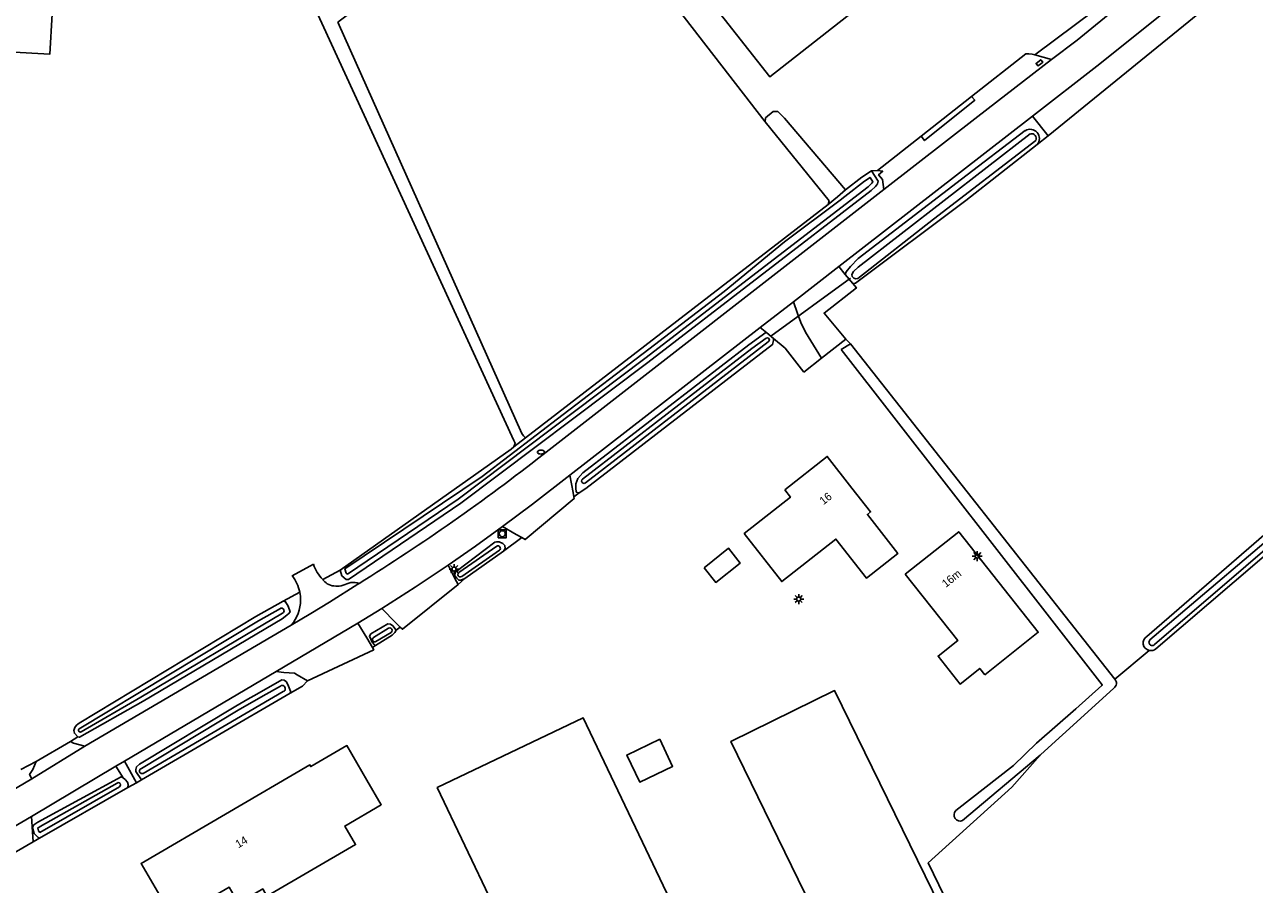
# Model space of a CAD drawing. Extents: x 141000 to 143000, y 400580 to 403500.
# Drawn here: x 141831.6 to 141985.3, y 403128.9 to 403236.3 of the extents above; entities that cross this region are included whole.
import ezdxf

# ---------------------------------------------------------------- set-up
doc = ezdxf.new("R2010")
doc.units = 0
for name, color, linetype in [('gg-afsc-erfafscheiding', 7, 'Continuous'), ('gg-anno-huisnummerreeks BGT', 7, 'Continuous'), ('gg-bbg-bijgebouw', 7, 'Continuous'), ('gg-bbg-gedigitaliseerde bebouwing', 7, 'Continuous'), ('gg-bbg-gedigitaliseerde bijgebouw', 7, 'Continuous'), ('gg-bbg-hoofdgebouw', 7, 'Continuous'), ('gg-knt-bronhoudergrens', 7, 'Continuous'), ('gg-knt-onverhard', 7, 'Continuous'), ('gg-knt-verharding', 7, 'Continuous'), ('gg-knt-verharding nz', 7, 'Continuous'), ('gg-kntw-bovenkant insteek waterloop', 7, 'Continuous'), ('gg-kntw-waterlijn', 7, 'Continuous'), ('gg-kwrk-duiker nz buis', 7, 'Continuous'), ('gt-grn-groengrens', 7, 'Continuous'), ('gt-grn-vlakafsluiter', 7, 'Continuous'), ('gt-symb-brandkraan', 7, 'Continuous'), ('gt-symb-kolk', 7, 'Continuous'), ('gt-symb-lichtmast', 7, 'Continuous'), ('gt-symb-rioolschacht', 7, 'Continuous'), ('gx-grn-maaiveld', 7, 'Continuous')]:
    doc.layers.add(name, color=color, linetype=linetype)

# ---------------------------------------------------------------- blocks, each defined once
blk = doc.blocks.new('gt0-KOLK')
at = {"layer": 'gt-symb-kolk'}
blk.add_lwpolyline([(0, 0), (0.37, 0), (0.37, 0.4), (-0.38, 0.4), (-0.38, 0), (0, 0)], dxfattribs=at)
blk = doc.blocks.new('gt0-LMAST')
at = {"layer": 'gt-symb-lichtmast'}
for p, q in [((-0.18, 0.17), (-0.45, 0.44)), ((-0.01, 0.25), (-0.01, 0.62)), ((0.17, 0.17), (0.44, 0.44)), ((-0.26, 0), (-0.63, 0)), ((-0.18, -0.18), (-0.45, -0.45)), ((-0.01, -0.25), (-0.01, -0.63)), ((0.44, -0.45), (0.17, -0.18)), ((0.24, 0), (0.62, 0))]:
    blk.add_line(p, q, dxfattribs=at)
blk.add_circle((-0.01, 0), 0.25, dxfattribs=at)
blk = doc.blocks.new('gt0-RS')
at = {"layer": 'gt-symb-rioolschacht'}
blk.add_lwpolyline([(-0.5, -0.5), (0.5, -0.5), (0.5, 0.5), (-0.5, 0.5)], close=True, dxfattribs=at)
blk.add_circle((0, 0), 0.375, dxfattribs=at)
blk = doc.blocks.new('gt0-BR')
at = {"layer": 'gt-symb-brandkraan'}
for centre, radius, start, end in [((-0.24, 0), 0.206, 107.5669, 252.4331), ((0.6, -2.66), 3, 106.892, 107.5669), ((0, -0.69), 0.938, 73.108, 106.892), ((-0.6, -2.66), 3, 72.4331, 73.108), ((0.24, 0), 0.206, 287.567, 72.4331), ((0.6, 2.66), 3, 252.4331, 253.108), ((0, 0.69), 0.938, 253.108, 286.8921), ((-0.6, 2.66), 3, 286.8921, 287.567)]:
    blk.add_arc(centre, radius, start, end, dxfattribs=at)

msp = doc.modelspace()

# ---------------------------------------------------------------- linework, layer by layer
at = {"layer": 'gg-afsc-erfafscheiding'}
for p, q in [((141900.92, 403177.77), (141900.27, 403177.27)), ((141891.48, 403170.47), (141893.77, 403172.17)), ((141871.09, 403168.12), (141868.9, 403166.93)), ((141885.81, 403166.33), (141886.65, 403167.08)), ((141866.02, 403165.36), (141863.93, 403164.22)), ((141878.05, 403160.62), (141878.59, 403160.98)), ((141875.11, 403158.45), (141875.49, 403158.68)), ((141838.3, 403147.27), (141837.37, 403146.71)), ((141833.1, 403144.23), (141831.19, 403143.2)), ((141845.64, 403141.56), (141846.26, 403141.91))]:
    msp.add_line(p, q, dxfattribs=at)
for points in [[(141866.97, 403154.3), (141866.35, 403153.64), (141864.84, 403152.76)], [(141832.7, 403134.18), (141833.19, 403134.45), (141833.5, 403134.63)]]:
    msp.add_lwpolyline(points, dxfattribs=at)
at = {"layer": 'gg-bbg-bijgebouw'}
for points in [[(141941.69, 403243.44), (141941.31, 403243.14), (141941.51, 403242.89), (141924.77, 403229.72), (141899.31, 403262.09), (141893.11, 403269.97), (141908.55, 403282.12), (141916.57, 403271.93), (141919.27, 403274.05), (141925.15, 403266.58)], [(141948.89, 403120.32), (141935.9, 403113.96), (141919.89, 403146.72), (141932.85, 403153.07), (141948.89, 403120.32)], [(141905.07, 403098.82), (141921.87, 403106.83), (141901.44, 403149.65), (141883.2, 403140.95), (141893.56, 403119.24), (141895, 403119.93), (141905.07, 403098.82)]]:
    msp.add_lwpolyline(points, dxfattribs=at)
at = {"layer": 'gg-bbg-gedigitaliseerde bebouwing'}
msp.add_lwpolyline([(141941.67, 403167.6), (141948.24, 403159.31), (141945.78, 403157.37), (141948.54, 403153.89), (141950.99, 403155.83), (141951.61, 403155.05)], dxfattribs=at)
at = {"layer": 'gg-bbg-gedigitaliseerde bijgebouw'}
for points in [[(141916.55, 403168.42), (141919.61, 403170.84), (141921.06, 403169), (141918, 403166.58), (141916.55, 403168.42)], [(141911, 403146.98), (141906.89, 403145.02), (141908.51, 403141.63), (141912.61, 403143.59), (141911, 403146.98)]]:
    msp.add_lwpolyline(points, dxfattribs=at)
at = {"layer": 'gg-bbg-hoofdgebouw'}
for points in [[(141834.07, 403278.36), (141836.96, 403278.24), (141836.92, 403277.43), (141835.07, 403237.57), (141834.8, 403232.58), (141823.57, 403233.19), (141823.73, 403237.19)], [(141926.62, 403178.14), (141927.33, 403177.21), (141921.56, 403172.68), (141926.24, 403166.69), (141933.01, 403171.99), (141936.82, 403167.11), (141940.76, 403170.2), (141936.95, 403175.07), (141937.35, 403175.39), (141935.02, 403178.37), (141931.94, 403182.31), (141926.62, 403178.14)], [(141951.61, 403155.05), (141958.31, 403160.36), (141948.37, 403172.91), (141941.67, 403167.6)], [(141861.92, 403127.39), (141872.99, 403133.84), (141871.64, 403136.15), (141876.21, 403138.81), (141874.42, 403141.87), (141871.92, 403146.19), (141867.4, 403143.58), (141867.29, 403143.78), (141846.19, 403131.47), (141850.28, 403124.47), (141857.21, 403128.51), (141858.37, 403126.52), (141861.4, 403128.29), (141861.92, 403127.39)]]:
    msp.add_lwpolyline(points, dxfattribs=at)
at = {"layer": 'gg-knt-bronhoudergrens'}
msp.add_line((141958.17, 403221.26), (141959.55, 403222.38), dxfattribs=at)
for points in [[(141924.18, 403224.13), (141898.5, 403257.31), (141870.76, 403236.56)], [(141958.55, 403144.99), (141955.02, 403141.02), (141944.55, 403131.54), (141954.01, 403112.06), (141957.01, 403108.48), (141960.13, 403104.76), (141962.3, 403102.46), (141965.5, 403098.58), (141966.12, 403097.9), (141967.07, 403095.33), (141975.4, 403078.56), (141957.18, 403069.55)]]:
    msp.add_lwpolyline(points, dxfattribs=at)
at = {"layer": 'gg-knt-onverhard'}
for p, q in [((141959.55, 403222.38), (141985.09, 403243.14)), ((141967.88, 403154.5), (141972.18, 403158.08))]:
    msp.add_line(p, q, dxfattribs=at)
at = {"layer": 'gg-knt-verharding'}
for p, q in [((141959.94, 403231.88), (141957.87, 403232.46)), ((141933.38, 403206.04), (141957.57, 403224.81)), ((141957.57, 403224.81), (141959.55, 403222.38)), ((141938.99, 403215.66), (141896.44, 403182.55)), ((141927.7, 403201.63), (141933.38, 403206.04)), ((141933.38, 403206.04), (141934.19, 403205.06)), ((141934.19, 403205.06), (141935.15, 403203.9)), ((141927.7, 403201.63), (141923.57, 403198.42)), ((141899.77, 403179.96), (141923.57, 403198.42)), ((141923.57, 403198.42), (141924.39, 403197.74)), ((141924.39, 403197.74), (141925.21, 403197.05)), ((141934.24, 403196.97), (141931.22, 403194.58)), ((141865.06, 403167.42), (141867.72, 403168.85)), ((141871.18, 403166.17), (141872.4, 403166.57)), ((141873.29, 403161.48), (141876.28, 403163.33)), ((141864.97, 403161.25), (141839.16, 403146.11)), ((141844.12, 403144.24), (141863.08, 403155.44)), ((141837.37, 403146.71), (141833.1, 403144.23)), ((141844.12, 403144.24), (141845.64, 403141.56)), ((141832.49, 403137.36), (141843.06, 403143.61)), ((141843.06, 403143.61), (141843.97, 403142.19)), ((141832.54, 403142.06), (141787.23, 403115.41)), ((141844.55, 403140.98), (141845.64, 403141.56))]:
    msp.add_line(p, q, dxfattribs=at)
for points in [[(141968.4, 403238.58), (141963.18, 403234.3), (141959.94, 403231.88)], [(141959.94, 403231.88), (141950.76, 403224.79), (141938.99, 403215.66)], [(141957.87, 403232.46), (141957.56, 403232.55), (141957.12, 403232.6), (141956.74, 403232.61)], [(141949.97, 403227.29), (141950.37, 403226.8), (141944.09, 403221.76), (141943.67, 403222.33)], [(141938.99, 403215.66), (141938.84, 403216.89), (141938.34, 403217.51), (141938.87, 403217.93), (141938.23, 403218.05)], [(141935.15, 403203.9), (141935.58, 403203.37), (141931.55, 403200.22), (141934.24, 403196.97)], [(141927.7, 403201.63), (141928.23, 403200.18), (141928.64, 403199.05)], [(141931.22, 403194.58), (141929.21, 403197.82), (141928.64, 403199.05)], [(141925.21, 403197.05), (141926.69, 403195.82), (141929.03, 403192.86)], [(141899.77, 403179.96), (141900.17, 403177.8), (141900.27, 403177.27)], [(141900.27, 403177.27), (141900.31, 403177.04), (141894.2, 403171.92), (141893.77, 403172.17)], [(141884.55, 403168.73), (141887.97, 403171.11), (141891.36, 403173.55)], [(141891.36, 403173.55), (141893.06, 403172.58), (141893.77, 403172.17)], [(141884.55, 403168.73), (141885.42, 403167.08), (141885.81, 403166.33)], [(141878.59, 403160.98), (141878.86, 403160.72), (141885.81, 403166.33)], [(141876.28, 403163.33), (141878.03, 403161.55), (141878.59, 403160.98)], [(141873.29, 403161.48), (141874.39, 403159.64), (141875.11, 403158.45)], [(141875.11, 403158.45), (141875.27, 403158.17), (141866.97, 403154.3)], [(141863.08, 403155.44), (141864.04, 403155.31), (141865.38, 403155.23), (141865.71, 403155.04), (141866.97, 403154.3)], [(141839.16, 403146.11), (141837.74, 403146.52), (141837.37, 403146.71)], [(141832.54, 403142.06), (141832.26, 403142.57), (141832.66, 403143.19), (141833.1, 403144.23)], [(141832.49, 403137.36), (141832.62, 403135.43), (141832.7, 403134.18)], [(141832.7, 403134.18), (141826.43, 403130.55), (141826.14, 403130.74)]]:
    msp.add_lwpolyline(points, dxfattribs=at)
for centre, radius, start, end in [((141735.06, 403388.54), 261.67, 301.923, 308.0774), ((141872.96, 403170.74), 5.57, 199.8394, 223.2194), ((141861.22, 403164.37), 4.91, 11.6057, 38.4918), ((141872.99, 403170.75), 5.6, 223.1468, 230.9856), ((141870.64, 403168.63), 2.52, 242.0676, 282.3455), ((141872.72, 403164.95), 1.64, 64.4544, 101.2682), ((141861.33, 403164.37), 4.79, 319.4025, 359.974), ((141861.21, 403164.37), 4.91, 359.9744, 11.5846)]:
    msp.add_arc(centre, radius, start, end, dxfattribs=at)
at = {"layer": 'gg-knt-verharding nz'}
for p, q in [((141863.08, 403155.44), (141873.29, 403161.48)), ((141839.16, 403146.11), (141832.54, 403142.06)), ((141843.06, 403143.61), (141844.12, 403144.24)), ((141823.9, 403132.28), (141832.49, 403137.36))]:
    msp.add_line(p, q, dxfattribs=at)
for points in [[(141957.57, 403224.81), (141965.64, 403231.07), (141973.71, 403237.51), (141983.27, 403245.36)], [(141891.36, 403173.55), (141895.12, 403176.35), (141899.77, 403179.96)], [(141876.28, 403163.33), (141880.44, 403165.99), (141884.55, 403168.73)], [(141873.43, 403166.44), (141873.27, 403166.34), (141869.72, 403164.13), (141867.42, 403162.69), (141864.97, 403161.25)]]:
    msp.add_lwpolyline(points, dxfattribs=at)
at = {"layer": 'gg-kntw-bovenkant insteek waterloop'}
for p, q in [((141932.03, 403213.79), (141894.24, 403184.64)), ((141935.15, 403203.9), (141935.48, 403203.95)), ((141933.67, 403195.66), (141934.83, 403196.37)), ((141967.88, 403154.5), (141934.83, 403196.37)), ((141886.65, 403167.08), (141891.48, 403170.47)), ((141967.74, 403153.38), (141964.04, 403150.01)), ((141846.26, 403141.91), (141864.84, 403152.76)), ((141958.63, 403145.07), (141964.04, 403150.01)), ((141958.55, 403144.99), (141948.83, 403136.84)), ((141844.55, 403140.98), (141833.5, 403134.63))]:
    msp.add_line(p, q, dxfattribs=at)
for points in [[(141892.76, 403183.52), (141892.92, 403183.97), (141892.78, 403184.3), (141859.92, 403255.74)], [(141870.76, 403236.56), (141893.76, 403185.18), (141894, 403184.88), (141894.24, 403184.64)], [(141924.18, 403224.13), (141924.24, 403224.6), (141925.18, 403225.42), (141925.76, 403225.39), (141926.61, 403224.55), (141934.22, 403215.6)], [(141924.18, 403224.13), (141932.16, 403214.26), (141932.03, 403213.79)], [(141956.67, 403223.01), (141948.7, 403216.94), (141935.81, 403207.03), (141934.86, 403206.06), (141934.3, 403205.38), (141934.19, 403205.06)], [(141958.17, 403221.26), (141949.25, 403214.27), (141935.48, 403203.95)], [(141871.09, 403168.12), (141871.3, 403167.41), (141871.82, 403166.96), (141872.11, 403166.96), (141886.17, 403176.47), (141909.51, 403194.05), (141937.41, 403215.53), (141937.97, 403216.04), (141938.21, 403216.38), (141938.3, 403216.7), (141937.45, 403218)], [(141937.45, 403218), (141936.24, 403217.18), (141934.22, 403215.6)], [(142018.46, 403199.94), (142002.95, 403186.55), (141991.15, 403176.51), (141971.88, 403159.84)], [(141900.92, 403177.77), (141900.58, 403177.86), (141900.51, 403178.39), (141900.52, 403178.91), (141900.78, 403179.57), (141901.4, 403180.27), (141922.14, 403196.26), (141924.28, 403197.8), (141924.39, 403197.74)], [(141900.92, 403177.77), (141901.76, 403178.29), (141925.11, 403196.29), (141925.21, 403196.81)], [(141925.21, 403197.05), (141925.24, 403196.97), (141925.21, 403196.81)], [(141972.99, 403158.3), (141996.01, 403177.99), (142018.71, 403197.66)], [(141933.67, 403195.66), (141966.29, 403153.8), (141966.24, 403153.71), (141963, 403150.8)], [(141871.09, 403168.12), (141892.45, 403183.22), (141892.76, 403183.52)], [(141886.65, 403167.08), (141886.16, 403166.86), (141885.89, 403166.84), (141885.64, 403167.09), (141885.4, 403167.39), (141885.44, 403167.82), (141885.58, 403167.96), (141890.4, 403171.6), (141890.63, 403171.66), (141890.95, 403171.66), (141891.41, 403171.42), (141891.63, 403171.2), (141891.7, 403170.81), (141891.48, 403170.47)], [(141863.93, 403164.22), (141860.55, 403162.32), (141838.47, 403149.01), (141838.13, 403148.73), (141837.93, 403148.44), (141837.81, 403148.1), (141837.86, 403147.73), (141838.3, 403147.27)], [(141863.93, 403164.22), (141864.26, 403164.14), (141864.58, 403163.63), (141864.82, 403162.91), (141864.63, 403162.67), (141863.82, 403162.01), (141846.45, 403151.74), (141838.5, 403147.23), (141838.3, 403147.27)], [(141875.49, 403158.68), (141875.35, 403158.78), (141875.08, 403159.12), (141874.72, 403159.86), (141874.89, 403160.15), (141877.04, 403161.4), (141877.38, 403161.38), (141877.67, 403161.17), (141878.05, 403160.62)], [(141875.49, 403158.68), (141877.59, 403160.01), (141877.89, 403160.32), (141878.05, 403160.62)], [(141846.26, 403141.91), (141845.54, 403142.95), (141845.53, 403143.21), (141845.62, 403143.53), (141846, 403143.89), (141858.03, 403151.13), (141859.54, 403151.99), (141860.64, 403152.62), (141863.77, 403154.42), (141864.07, 403154.36), (141864.35, 403154.15), (141864.62, 403153.62), (141864.87, 403152.99), (141864.84, 403152.76)], [(141948, 403138.08), (141955.2, 403143.73), (141958.08, 403146.52), (141963, 403150.8)], [(141843.97, 403142.19), (141843.69, 403142.29), (141833.29, 403136.62), (141832.79, 403136.29), (141832.63, 403135.95), (141832.85, 403135.22), (141833.32, 403134.73), (141833.5, 403134.63)], [(141843.97, 403142.19), (141844.2, 403141.97), (141844.48, 403141.61), (141844.58, 403141.33), (141844.55, 403140.98)]]:
    msp.add_lwpolyline(points, dxfattribs=at)
for centre, radius, start, end in [((141957.29, 403222.02), 1.16, 319.2169, 122.1697), ((141972.36, 403159.02), 0.953, 120.581, 259.1891), ((141972.36, 403159.01), 0.951, 259.0879, 311.1816), ((141967.35, 403153.99), 0.728, 302.6729, 43.9609), ((141948.53, 403137.53), 0.76, 134.2425, 293.4564)]:
    msp.add_arc(centre, radius, start, end, dxfattribs=at)
at = {"layer": 'gg-kntw-waterlijn'}
for p, q in [((141924.56, 403196.62), (141901.72, 403179.01)), ((141892.76, 403183.52), (141894.24, 403184.64)), ((141890.64, 403171.11), (141885.92, 403167.82)), ((141886.26, 403167.32), (141890.98, 403170.62)), ((141877.12, 403160.86), (141875.22, 403159.69)), ((141877.44, 403160.34), (141875.54, 403159.18)), ((141846.44, 403142.71), (141863.97, 403152.95))]:
    msp.add_line(p, q, dxfattribs=at)
for points in [[(141957.99, 403221.79), (141945.2, 403211.96), (141935.75, 403204.55), (141935.5, 403204.49), (141935.27, 403204.6), (141935.05, 403204.79), (141935.01, 403205.02), (141935.23, 403205.4), (141935.81, 403205.95), (141957.31, 403222.6)], [(141871.99, 403167.61), (141871.82, 403167.75), (141871.66, 403168.29), (141888.82, 403179.82), (141898.93, 403187.55), (141909.63, 403195.73), (141919.04, 403202.92), (141926.6, 403209.11), (141933.55, 403214.33), (141934.13, 403214.77), (141936.59, 403216.69), (141937.28, 403217.16), (141937.64, 403216.61), (141937.52, 403216.44), (141937.03, 403215.99), (141909.15, 403194.53), (141885.82, 403176.96), (141871.99, 403167.61)], [(141932.03, 403213.79), (141933.2, 403214.76), (141934.22, 403215.6)], [(142018.3, 403198.99), (142003.33, 403186.1), (141991.69, 403175.88), (141972.26, 403159.39)], [(142018.53, 403198.24), (141995.65, 403178.4), (141972.83, 403158.81)], [(141924.32, 403197.09), (141922.5, 403195.78), (141901.37, 403179.49)], [(141863.61, 403163.34), (141860.86, 403161.8), (141838.46, 403148.31)], [(141863.87, 403162.74), (141846.15, 403152.26), (141838.7, 403147.92)], [(141863.62, 403153.64), (141861.45, 403152.4), (141858.34, 403150.61), (141846.23, 403143.33)], [(141843.19, 403141.52), (141833.6, 403136.11), (141833.28, 403135.89), (141833.38, 403135.53), (141833.55, 403135.35), (141843.49, 403141.06)]]:
    msp.add_lwpolyline(points, dxfattribs=at)
for centre, radius, start, end in [((141957.5, 403222.06), 0.563, 331.081, 109.0329), ((141924.44, 403196.86), 0.26, 295.984, 118.0337), ((141901.54, 403179.25), 0.297, 125.5828, 306.8833), ((141890.79, 403170.85), 0.301, 309.1925, 120.5724), ((141886.07, 403167.56), 0.301, 120.8156, 308.9493), ((141863.73, 403163.04), 0.332, 294.8172, 112.4416), ((141877.28, 403160.6), 0.3, 300.5625, 122.3148), ((141875.39, 403159.44), 0.3, 123.3444, 299.6326), ((141972.54, 403159.09), 0.405, 132.9184, 315.8796), ((141863.83, 403153.31), 0.39, 290.9612, 122.961), ((141838.6, 403148.12), 0.229, 126.7942, 297.8018), ((141846.33, 403143.02), 0.329, 108.1037, 288.7662), ((141843.35, 403141.3), 0.272, 299.5093, 126.1134)]:
    msp.add_arc(centre, radius, start, end, dxfattribs=at)
at = {"layer": 'gg-kwrk-duiker nz buis'}
msp.add_line((141924.9, 403197.35), (141934.85, 403204.6), dxfattribs=at)
at = {"layer": 'gt-grn-groengrens'}
for p, q in [((141943.67, 403222.33), (141949.97, 403227.29)), ((141938.23, 403218.05), (141937.45, 403218)), ((141934.24, 403196.97), (141934.83, 403196.37))]:
    msp.add_line(p, q, dxfattribs=at)
msp.add_lwpolyline([(141957.87, 403232.46), (141965.42, 403238.12), (141967.83, 403240.12), (141968.14, 403240.97), (141968.15, 403241.59), (141968.54, 403241.9)], dxfattribs=at)
at = {"layer": 'gt-grn-vlakafsluiter'}
for p, q in [((141949.97, 403227.29), (141956.74, 403232.61)), ((141938.23, 403218.05), (141943.67, 403222.33)), ((141931.22, 403194.58), (141929.03, 403192.86))]:
    msp.add_line(p, q, dxfattribs=at)
at = {"layer": 'gx-grn-maaiveld'}
msp.add_line((141958.55, 403144.99), (141958.63, 403145.07), dxfattribs=at)

# ---------------------------------------------------------------- block references
at = {"layer": 'gt-symb-brandkraan'}
msp.add_blockref('gt0-BR', (141896.17, 403182.86), dxfattribs=at)
at = {"layer": 'gt-symb-kolk', "rotation": 37.49774051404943}
msp.add_blockref('gt0-KOLK', (141958.57, 403231.33), dxfattribs=at)
at = {"layer": 'gt-symb-lichtmast'}
for p in [(141950.69, 403169.86), (141885.32, 403168.25), (141928.38, 403164.5)]:
    msp.add_blockref('gt0-LMAST', p, dxfattribs=at)
at = {"layer": 'gt-symb-rioolschacht'}
msp.add_blockref('gt0-RS', (141891.33, 403172.66), dxfattribs=at)

# ---------------------------------------------------------------- texts
at = {"layer": 'gg-anno-huisnummerreeks BGT'}
for s, rotation, p in [('16', 38.1, (141931.45, 403176.21)), ('16m', 38.4, (141946.75, 403165.88)), ('14', 30.3, (141858.34, 403133.35))]:
    msp.add_text(s, height=1, rotation=rotation, dxfattribs=at).set_placement(p)

doc.saveas('drawing.dxf')
